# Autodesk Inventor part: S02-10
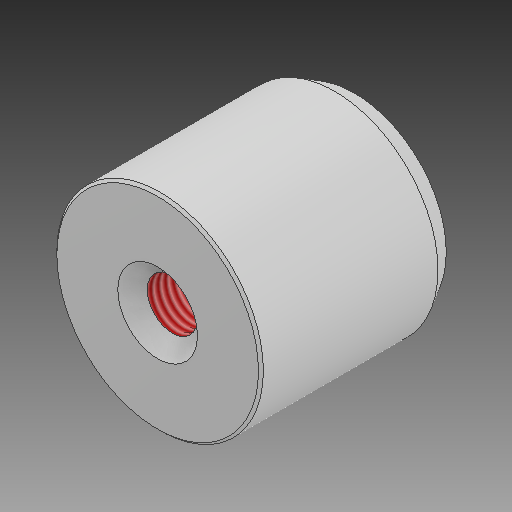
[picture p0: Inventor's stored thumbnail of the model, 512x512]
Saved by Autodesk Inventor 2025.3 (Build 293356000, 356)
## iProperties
Created: 2025-04
Part Number: S02-10
Material: Všeobecné
Document SubType Name: Modeling
Designer: Patrik
Density: 1 g/cm^3
Appearance: Výchozí
Description: Centrovací pouzdro se dvěma lícovacími průměry
Stock Number: E 1160/42x40
User Status: 1.7131
Author: Patrik
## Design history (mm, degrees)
feature "Base1"
feature "Závit1" dims "d0" = 8.418, "d1" = 0
node "Těleso1"
